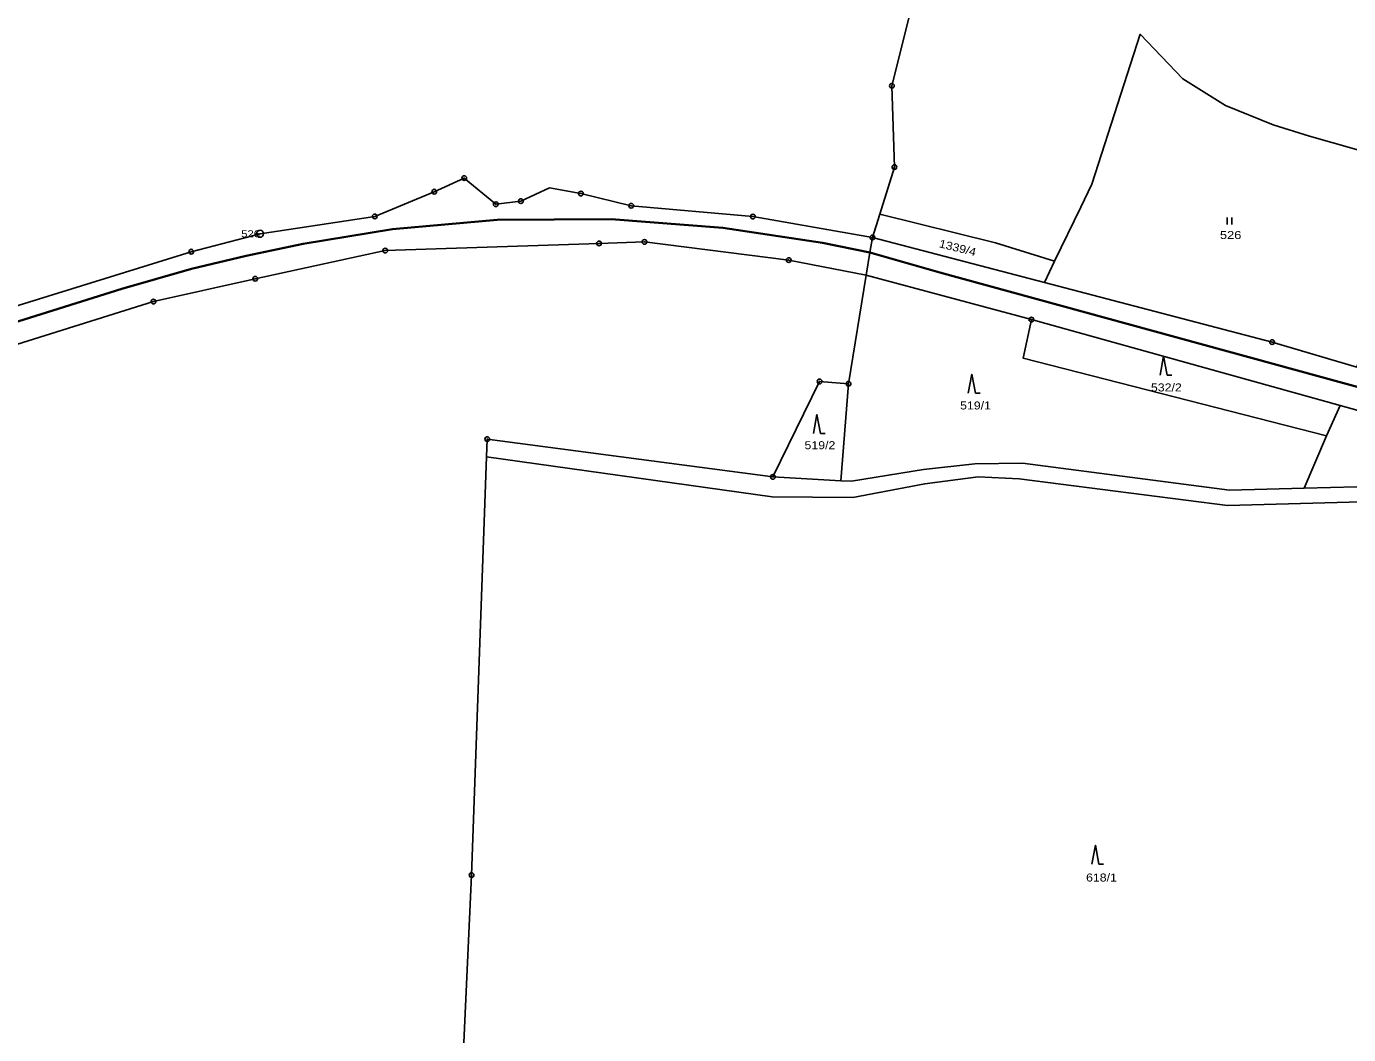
# Model space of a CAD drawing. Extents: x -872229 to -869198, y -1075981 to -1074329.
# Drawn here: x -870040 to -869759.2, y -1075531.8 to -1075317.7 of the extents above; entities that cross this region are included whole.
import ezdxf
from ezdxf.enums import TextEntityAlignment as Align

# ---------------------------------------------------------------- set-up
doc = ezdxf.new("R2010")
doc.units = 0
doc.header["$LTSCALE"] = 0.68
for name, color, linetype, lineweight in [('1', 7, 'Continuous', 25), ('3', 7, 'Continuous', 25), ('6', 7, 'Continuous', 25), ('8', 7, 'Continuous', 25)]:
    doc.layers.add(name, color=color, linetype=linetype, lineweight=lineweight)
doc.layers.add('2', color=7, linetype='Continuous')

msp = doc.modelspace()

# ---------------------------------------------------------------- linework, layer by layer
at = {"layer": '1'}
for p, q in [((-869858.81, -1075357.57), (-869860.35, -1075362.51)), ((-869823.79, -1075372.09), (-869860.35, -1075362.51)), ((-869826.6, -1075379.98), (-869861.67, -1075370.56)), ((-869760.99, -1075398.24), (-869826.6, -1075379.98)), ((-869865.43, -1075393.59), (-869867.09, -1075414.18)), ((-869694.77, -1075416.68), (-869760.99, -1075398.24)), ((-869763.88, -1075404.68), (-869768.68, -1075415.77))]:
    msp.add_line(p, q, dxfattribs=at)
for points in [[(-869786.75, -1075258.83), (-869811.82, -1075270.12), (-869821.36, -1075282.34), (-869814.57, -1075302.35), (-869843.97, -1075292.89), (-869846.6, -1075291.84), (-869856.2, -1075330.32)], [(-869742.8, -1075348.02), (-869767.51, -1075341.02), (-869775.27, -1075338.64), (-869785.4, -1075334.51), (-869794.46, -1075328.86), (-869803.48, -1075319.37), (-869813.74, -1075351.24), (-869816.07, -1075356.1), (-869821.67, -1075367.58)], [(-869856.2, -1075330.32), (-869855.68, -1075347.57), (-869858.81, -1075357.57)], [(-870067.91, -1075385.07), (-870005.01, -1075365.55), (-869990.41, -1075361.75), (-869966.05, -1075358.08), (-869953.4, -1075352.81), (-869947.04, -1075349.93), (-869940.35, -1075355.49), (-869935.02, -1075354.82), (-869928.93, -1075352), (-869922.26, -1075353.21), (-869911.58, -1075355.81), (-869885.74, -1075358.09), (-869860.35, -1075362.51)], [(-869821.67, -1075367.58), (-869823.79, -1075372.09), (-869775.47, -1075384.75), (-869757.47, -1075390.06), (-869742.8, -1075348.02)], [(-869858.81, -1075357.57), (-869834.21, -1075363.69), (-869821.67, -1075367.58)], [(-869861.67, -1075370.56), (-869878.14, -1075367.33), (-869908.77, -1075363.47), (-869918.42, -1075363.79), (-869963.81, -1075365.31), (-869991.44, -1075371.29), (-870013.06, -1075376.14), (-870080.98, -1075397.47), (-870137.41, -1075416.91), (-870198.36, -1075434.14), (-870229.56, -1075445.28), (-870312.6, -1075469.56), (-870365.19, -1075486.42), (-870398.17, -1075493.93), (-870445.72, -1075497.57), (-870473.49, -1075498.03), (-870483.95, -1075496.85)], [(-869860.35, -1075362.51), (-869860.88, -1075365.74), (-869861.67, -1075370.56)], [(-869881.5, -1075413.38), (-869871.59, -1075393.12), (-869865.43, -1075393.59), (-869861.67, -1075370.56)], [(-869826.6, -1075379.98), (-869828.36, -1075388.16), (-869763.88, -1075404.68), (-869760.99, -1075398.24)], [(-869942.3, -1075409.15), (-869942.16, -1075405.35), (-869881.5, -1075413.38)], [(-869956.21, -1075634.42), (-869950.93, -1075616.94), (-869945.48, -1075497.93), (-869942.3, -1075409.15)], [(-869633.9, -1075448.79), (-869640.35, -1075447.27), (-869661.71, -1075443.1), (-869696.29, -1075431.95), (-869735.78, -1075418.09), (-869784.91, -1075419.45), (-869829.22, -1075413.77), (-869837.88, -1075413.34), (-869849.23, -1075414.84), (-869864.5, -1075417.75), (-869881.67, -1075417.62), (-869942.3, -1075409.15)], [(-869768.68, -1075415.77), (-869784.54, -1075416.18), (-869828.48, -1075410.47), (-869838.61, -1075410.64), (-869849.53, -1075411.78), (-869864.81, -1075414.31), (-869867.09, -1075414.18), (-869881.5, -1075413.38)], [(-869693.4, -1075428.58), (-869694.91, -1075424.51), (-869690.98, -1075417.73), (-869694.77, -1075416.68), (-869700.66, -1075426.2), (-869735.08, -1075414.89), (-869768.68, -1075415.77)]]:
    msp.add_lwpolyline(points, dxfattribs=at)
at = {"layer": '3'}
for p, q in [((-869784.991, -1075359.78), (-869784.991, -1075358.28)), ((-869783.99, -1075359.78), (-869783.99, -1075358.28)), ((-869797.77, -1075391.77), (-869796.774, -1075391.77)), ((-869838.49, -1075395.58), (-869837.494, -1075395.58)), ((-869871.38, -1075404.14), (-869870.384, -1075404.14)), ((-869812.26, -1075495.59), (-869811.264, -1075495.59))]:
    msp.add_line(p, q, dxfattribs=at)
for points in [[(-869797.77, -1075391.77), (-869798.52, -1075387.77), (-869799.27, -1075391.77)], [(-869838.49, -1075395.58), (-869839.24, -1075391.58), (-869839.99, -1075395.58)], [(-869871.38, -1075404.14), (-869872.13, -1075400.14), (-869872.88, -1075404.14)], [(-869812.26, -1075495.59), (-869813.01, -1075491.59), (-869813.76, -1075495.59)]]:
    msp.add_lwpolyline(points, dxfattribs=at)
at = {"layer": '6', "lineweight": 35}
for p, q in [((-869981.25, -1075363.9), (-869962.25, -1075360.77)), ((-870019.78, -1075373.46), (-870004.94, -1075369.18))]:
    msp.add_line(p, q, dxfattribs=at)
for points in [[(-869962.25, -1075360.77), (-869940.06, -1075358.8), (-869915.83, -1075358.65), (-869892.09, -1075360.5), (-869870.97, -1075363.66), (-869860.88, -1075365.74)], [(-870004.94, -1075369.18), (-869993.36, -1075366.4), (-869981.25, -1075363.9)], [(-869860.88, -1075365.74), (-869846.01, -1075369.94), (-869704.43, -1075408.78), (-869641.66, -1075426.07), (-869625.84, -1075430.18), (-869607.72, -1075434.15), (-869580.2, -1075438.82), (-869542.66, -1075442.5), (-869518.18, -1075443.57), (-869485.71, -1075443.04), (-869459.17, -1075441.98), (-869409.77, -1075437.63)], [(-870103.28, -1075399.64), (-870067.42, -1075388.4), (-870019.78, -1075373.46)]]:
    msp.add_lwpolyline(points, dxfattribs=at)
at = {"layer": '8'}
for centre, radius in [((-869856.2, -1075330.3199), 0.5), ((-869856.2, -1075330.3199), 0.0303), ((-869855.68, -1075347.5699), 0.5), ((-869947.04, -1075349.9299), 0.5), ((-869947.04, -1075349.9299), 0.0303), ((-869855.68, -1075347.5699), 0.0303), ((-869953.4, -1075352.8099), 0.5), ((-869953.4, -1075352.8099), 0.0303), ((-869922.26, -1075353.2099), 0.5), ((-869940.35, -1075355.4899), 0.5), ((-869940.35, -1075355.4899), 0.0303), ((-869935.02, -1075354.8199), 0.5), ((-869935.02, -1075354.8199), 0.0303), ((-869922.26, -1075353.2099), 0.0303), ((-869911.58, -1075355.8099), 0.5), ((-869911.58, -1075355.8099), 0.0303), ((-869966.05, -1075358.0799), 0.5), ((-869966.05, -1075358.0799), 0.0303), ((-869885.74, -1075358.0899), 0.5), ((-869885.74, -1075358.0899), 0.0303), ((-869990.41, -1075361.7498), 0.75), ((-869990.41, -1075361.7498), 0.03), ((-869918.42, -1075363.7899), 0.5), ((-869918.42, -1075363.7899), 0.0303), ((-869908.77, -1075363.4699), 0.5), ((-869908.77, -1075363.4699), 0.0303), ((-869860.35, -1075362.5099), 0.5), ((-869860.35, -1075362.5099), 0.0303), ((-870005.01, -1075365.5499), 0.5), ((-870005.01, -1075365.5499), 0.0303), ((-869963.81, -1075365.3099), 0.5), ((-869963.81, -1075365.3099), 0.0303), ((-869878.14, -1075367.3299), 0.5), ((-869878.14, -1075367.3299), 0.0303), ((-869991.44, -1075371.2899), 0.5), ((-869991.44, -1075371.2899), 0.0303), ((-870013.06, -1075376.1399), 0.5), ((-870013.06, -1075376.1399), 0.0303), ((-869826.6, -1075379.9799), 0.5), ((-869826.6, -1075379.9799), 0.0303), ((-869775.47, -1075384.7499), 0.5), ((-869775.47, -1075384.7499), 0.0303), ((-869871.59, -1075393.1199), 0.5), ((-869871.59, -1075393.1199), 0.0303), ((-869865.43, -1075393.5899), 0.5), ((-869865.43, -1075393.5899), 0.0303), ((-869942.16, -1075405.3499), 0.5), ((-869942.16, -1075405.3499), 0.0303), ((-869881.5, -1075413.3799), 0.5), ((-869881.5, -1075413.3799), 0.0303), ((-869945.48, -1075497.9299), 0.5), ((-869945.48, -1075497.9299), 0.0303)]:
    msp.add_circle(centre, radius, dxfattribs=at)

# ---------------------------------------------------------------- texts
at = {"layer": '2'}
for s, width, p in [('526', 1.2, (-869786.55, -1075362.86)), ('532/2', 1.15, (-869801.2, -1075395.23)), ('519/1', 1.15, (-869841.73, -1075399.06)), ('519/2', 1.15, (-869874.77, -1075407.5)), ('618/1', 1.15, (-869814.98, -1075499.31))]:
    msp.add_text(s, height=1.7, dxfattribs=dict(at, width=width)).set_placement(p)
at = {"layer": '2', "width": 1.15}
msp.add_text('1339/4', height=1.7, rotation=346, dxfattribs=at).set_placement((-869846.335, -1075364.584))
at = {"layer": '8', "width": 1.2}
msp.add_text('526', height=1.5, dxfattribs=at).set_placement((-869990.41, -1075362.5), align=Align.RIGHT)

doc.saveas('drawing.dxf')
